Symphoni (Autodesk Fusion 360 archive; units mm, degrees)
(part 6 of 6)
sketch "Sketch4" plane through (0, -1, 0) normal (0, -1, 0) x axis (1, 0, 0)
  line L1 (0, 5) -> (0, 35)
  line L2 (105, 0) -> (5, 0)
  line L3 (110, 35) -> (110, 5)
  line L4 (5, 40) -> (105, 40)
  line L5 (54.65, 25.9017) -> (54.65, 36.5017)
  line L6 (45.35, 25.9017) -> (54.65, 25.9017)
  line L7 (45.35, 36.5017) -> (45.35, 25.9017)
  line L8 (53.95, 37.2017) -> (46.05, 37.2017)
  line L9 (74.82, 26.0167) -> (28.79, 26.0167)
  line L10 (28.79, 26.0167) -> (74.82, 26.0167)
  line L11 (51, 26.0167) -> (49, 26.0167)
  line L12 (51, 26.0167) -> (49, 26.0167)
  line L13 (35.39, 26.0167) -> (32.29, 26.0167)
  line L14 (70.38, 26.0167) -> (67.28, 26.0167)
  line L15 (74.82, 24.5067) -> (28.79, 24.5067)
  line L16 (28.79, 24.5067) -> (74.82, 24.5067)
  line L17 (51, 24.5067) -> (49, 24.5067)
  line L18 (51, 24.5067) -> (49, 24.5067)
  line L19 (35.39, 24.5067) -> (32.29, 24.5067)
  line L20 (70.38, 24.5067) -> (67.28, 24.5067)
  line L21 (86.536, 12.3973) -> (88.536, 12.3973)
  line L22 (86.536, 12.3973) -> (88.536, 12.3973)
  line L23 (31.001, 12.3973) -> (86.536, 12.3973)
  line L24 (29.001, 12.3973) -> (31.001, 12.3973)
  line L25 (29.001, 12.3973) -> (31.001, 12.3973)
  line L26 (86.536, 12.3973) -> (31.001, 12.3973)
  line L27 (36.646, 12.3973) -> (33.446, 12.3973)
  line L28 (47.606, 12.3973) -> (49.006, 12.3973)
  line L29 (50.146, 12.3973) -> (51.546, 12.3973)
  line L30 (52.686, 12.3973) -> (54.086, 12.3973)
  line L31 (74.256, 12.3973) -> (75.656, 12.3973)
  line L32 (74.256, 12.3973) -> (75.656, 12.3973)
  line L33 (74.256, 12.3973) -> (75.656, 12.3973)
  line L34 (85.736, 12.3973) -> (82.536, 12.3973)
  line L35 (74.256, 12.3973) -> (75.656, 12.3973)
  line L36 (74.256, 12.3973) -> (75.656, 12.3973)
  line L37 (74.256, 12.3973) -> (75.656, 12.3973)
  line L38 (36.736, 12.3973) -> (33.536, 12.3973)
  line L39 (78.096, 12.3973) -> (74.896, 12.3973)
  line L40 (86.536, 10.8873) -> (31.001, 10.8873)
  line L41 (74.82, 26.0167) -> (28.79, 26.0167)
  line L42 (74.82, 24.5067) -> (74.82, 26.0167)
  line L43 (28.79, 24.5067) -> (74.82, 24.5067)
  line L44 (28.79, 26.0167) -> (28.79, 24.5067)
  line L45 (86.536, 12.3973) -> (29.001, 12.3973)
  line L46 (86.536, 10.8873) -> (86.536, 12.3973)
  line L47 (29.001, 10.8873) -> (86.536, 10.8873)
  line L48 (29.001, 12.3973) -> (29.001, 10.8873)
  line L49 (35.39, 26.0167) -> (32.29, 26.0167)
  line L50 (36.646, 12.3973) -> (33.446, 12.3973)
  line L51 (36.736, 12.3973) -> (33.536, 12.3973)
  line L52 (85.736, 12.3973) -> (82.536, 12.3973)
  line L53 (78.096, 12.3973) -> (74.896, 12.3973)
  line L54 (37.4, 26.1067) -> (30.4005, 26.1067)
  line L55 (37.4, 29.975) -> (37.4, 26.1067)
  line L56 (30.4012, 29.975) -> (37.4, 29.975)
  line L57 (30.4012, 25.975) -> (30.4012, 29.975)
  line L58 (37.4313, 24.5067) -> (30.4313, 24.5067)
  line L59 (37.4313, 20.5067) -> (37.4313, 24.5067)
  line L60 (30.4313, 20.5067) -> (37.4313, 20.5067)
  line L61 (30.4313, 24.5067) -> (30.4313, 20.5067)
  line L62 (72.5068, 30.1067) -> (65.5068, 30.1067)
  line L63 (72.5068, 26.1067) -> (72.5068, 30.1067)
  line L64 (65.5068, 26.1067) -> (72.5068, 26.1067)
  line L65 (65.5068, 30.1067) -> (65.5068, 26.1067)
  line L66 (72.5068, 24.5067) -> (65.5068, 24.5067)
  line L67 (72.5068, 20.5067) -> (72.5068, 24.5067)
  line L68 (65.5068, 20.5067) -> (72.5068, 20.5067)
  line L69 (65.5068, 24.5067) -> (65.5068, 20.5067)
  line L70 (38.709, 12.3973) -> (31.709, 12.3973)
  line L71 (38.709, 15.3973) -> (38.709, 12.3973)
  line L72 (31.709, 15.3973) -> (38.709, 15.3973)
  line L73 (31.709, 12.3973) -> (31.709, 15.3973)
  line L74 (38.7054, 10.8873) -> (31.7054, 10.8873)
  line L75 (38.7054, 6.8873) -> (38.7054, 10.8873)
  line L76 (31.7054, 6.8873) -> (38.7054, 6.8873)
  line L77 (31.7054, 10.8873) -> (31.7054, 6.8873)
  arc A1 centre (5, 35) radius 5 clockwise from (0, 35) to (5, 40)
  arc A2 centre (5, 5) radius 5 clockwise from (5, 0) to (0, 5)
  arc A3 centre (105, 5) radius 5 clockwise from (110, 5) to (105, 0)
  arc A4 centre (105, 35) radius 5 clockwise from (105, 40) to (110, 35)
  arc A5 centre (46.05, 36.5017) radius 0.7 clockwise from (45.35, 36.5017) to (46.05, 37.2017)
  arc A6 centre (53.95, 36.5017) radius 0.7 clockwise from (53.95, 37.2017) to (54.65, 36.5017)
  circle C1 centre (50, 17.3288) radius 2.7
  point P31 (74.82, 24.5067)
  point P62 (74.82, 24.5067)
  point P22 (28.79, 26.0167)
  point P60 (28.79, 26.0167)
  point P59 (86.536, 10.8873)
  point P66 (86.536, 10.8873)
  point P41 (29.001, 12.3973)
  point P64 (29.001, 12.3973)
  point P82 (30.4313, 24.5067)
  point P90 (65.5068, 24.5067)
  point P94 (31.709, 12.3973)
  point P98 (31.7054, 10.8873)
  point P78 (30.4012, 25.975)
  point P79 (37.4, 26.1067)
  point P81 (30.4012, 29.975)
  point P83 (37.4313, 24.5067)
  point P85 (30.4313, 20.5067)
  point P86 (65.5068, 30.1067)
  point P87 (72.5068, 30.1067)
  point P89 (65.5068, 26.1067)
  point P91 (72.5068, 24.5067)
  point P93 (65.5068, 20.5067)
  point P95 (38.709, 12.3973)
  point P97 (31.709, 15.3973)
  point P99 (38.7054, 10.8873)
  point P101 (31.7054, 6.8873)
  horizontal L41
  vertical L42
  horizontal L43
  vertical L44
  coincident P31 P62
  coincident P22 P60
  horizontal L45
  vertical L46
  horizontal L47
  vertical L48
  coincident P59 P66
  coincident P41 P64
  horizontal L54
  vertical L55
  horizontal L56
  vertical L57
  horizontal L58
  vertical L59
  horizontal L60
  vertical L61
  coincident L43 P82
  horizontal L62
  vertical L63
  horizontal L64
  vertical L65
  horizontal L66
  vertical L67
  horizontal L68
  vertical L69
  coincident L43 P90
  horizontal L70
  vertical L71
  horizontal L72
  vertical L73
  coincident L23 P94
  horizontal L74
  vertical L75
  horizontal L76
  vertical L77
  coincident L40 P98
  collinear L65 L69
  dimension "d18" distance P78 P79 = 7
  dimension "d19" distance P78 P81 = 4
  dimension "d20" distance P82 P83 = 7
  dimension "d21" distance P82 P85 = 4
  dimension "d28" distance P86 P87 = 7
  dimension "d29" distance P86 P89 = 4
  dimension "d30" distance P90 P91 = 7
  dimension "d31" distance P90 P93 = 4
  dimension "d40" distance P94 P95 = 7
  dimension "d41" distance P94 P97 = 3
  dimension "d46" distance P98 P99 = 7
  dimension "d47" distance P98 P101 = 4
  dimension "d50" distance L43 L64 = 1.6
  dimension "d51" distance L43 L54 = 1.6
extrude "Extrude5" add sketch "Sketch4" profile of A6 L15 L16 L19 L20 L43 L58 L59 L60 L61 L66 L67 L68 L69 along normal blind 32
fillet "Fillet3" radius 2.5
fillet "Fillet4" radius 6
sketch "Sketch5" plane through (0, 0, 28.0167) normal (0, 0, 1) x axis (-1, 0, 0)
  line L1 (-30.473, 6) -> (-37.473, 6)
  line L2 (-30.473, 33) -> (-30.473, 6)
  line L3 (-37.473, 33) -> (-30.473, 33)
  line L4 (-37.473, 6) -> (-37.473, 33)
  circle C1 centre (-33.84, 30.11) radius 1.55
  circle C2 centre (-68.83, 30.11) radius 1.55
extrude "Extrude6" cut sketch "Sketch5" profile of C1 C2 against normal blind 8
sketch "Sketch6" plane through (0, 0, 12.3973) normal (0, 0, 1) x axis (-1, 0, 0)
  line L1 (-88.536, 4.4475) -> (-88.536, 48.4475)
  line L2 (-31.001, 2.4475) -> (-86.536, 2.4475)
  line L3 (-29.001, 48.4475) -> (-29.001, 4.4475)
  line L4 (-86.536, 50.4475) -> (-31.001, 50.4475)
  line L5 (-5, 1) -> (-5, 0)
  line L6 (-105, 1) -> (-5, 1)
  line L7 (-105, 0) -> (-105, 1)
  line L8 (-5, 0) -> (-105, 0)
  line L9 (-81, 13) -> (-81, 1)
  line L10 (-72.7669, 34.5764) -> (-81, 13)
  line L11 (-78.3852, 36.7202) -> (-72.7669, 34.5764)
  line L12 (-87.4363, 13) -> (-78.3852, 36.7202)
  line L13 (-87.4363, 1) -> (-87.4363, 13)
  arc A1 centre (-86.536, 48.4475) radius 2 clockwise from (-88.536, 48.4475) to (-86.536, 50.4475)
  arc A2 centre (-86.536, 4.4475) radius 2 clockwise from (-86.536, 2.4475) to (-88.536, 4.4475)
  arc A3 centre (-31.001, 4.4475) radius 2 clockwise from (-29.001, 4.4475) to (-31.001, 2.4475)
  arc A4 centre (-31.001, 48.4475) radius 2 clockwise from (-31.001, 50.4475) to (-29.001, 48.4475)
  circle C1 centre (-35.046, 9.8275) radius 1.6
  circle C2 centre (-48.306, 17.4675) radius 0.7
  circle C3 centre (-50.846, 17.4675) radius 0.7
  circle C4 centre (-53.386, 17.4675) radius 0.7
  circle C5 centre (-74.956, 4.1575) radius 0.7
  circle C6 centre (-74.956, 6.6975) radius 0.7
  circle C7 centre (-74.956, 9.2375) radius 0.7
  circle C8 centre (-84.136, 10.4175) radius 1.6
  circle C9 centre (-74.956, 11.7775) radius 0.7
  circle C10 centre (-74.956, 14.3175) radius 0.7
  circle C11 centre (-74.956, 16.8575) radius 0.7
  circle C12 centre (-35.136, 26.4875) radius 1.6
  circle C13 centre (-76.496, 33.2075) radius 1.6
  point P31 (-81, 1)
  point P36 (-87.4363, 1)
  coincident L6 P31
  perpendicular L6 L9
  perpendicular L10 L11
  perpendicular L11 L12
  coincident L6 P36
  perpendicular L6 L13
extrude "Extrude7" add sketch "Sketch6" profile of A2 L2 C8 C13 L6 L9 L10 L11 L12 L13 along normal blind 4
fillet "Fillet5" radius 2
extrude "Extrude8" add sketch "Sketch4" profile of A6 L23 L26 L27 L38 L40 L45 L47 L50 L51 L70 L71 L72 L73 L74 L75 L76 L77 along normal blind 29
fillet "Fillet6" radius 1.5 5
extrude "Extrude9" new body sketch "Sketch6" profile of A2 L2 C8 C13 L6 L9 L10 L11 L12 L13 blind -4 from offset -1.6
fillet "Fillet7" radius 1
extrude "Extrude10" cut sketch "Sketch6" profile of C1 C12 along normal blind 5 and against normal blind 10
sketch "Sketch7" plane through (0, -1, 0) normal (0, -1, 0) x axis (1, 0, 0)
  line L1 (31.7054, 10.8873) -> (31.7054, 1.8873)
  line L2 (38.7054, 10.8873) -> (31.7054, 10.8873)
  line L3 (38.7054, 1.8873) -> (38.7054, 10.8873)
  line L4 (31.7054, 1.8873) -> (38.7054, 1.8873)
  line L5 (38.709, 12.3973) -> (38.709, 16.8973)
  line L6 (31.709, 12.3973) -> (38.709, 12.3973)
  line L7 (31.709, 16.8973) -> (31.709, 12.3973)
  line L8 (38.709, 16.8973) -> (31.709, 16.8973)
  line L9 (87.4363, 12.3973) -> (87.4363, 18.3973)
  line L10 (81, 12.3973) -> (87.4363, 12.3973)
  line L11 (81, 18.3973) -> (81, 12.3973)
  line L12 (87.4363, 18.3973) -> (81, 18.3973)
  line L13 (65.5068, 24.5067) -> (65.5068, 14.5067)
  line L14 (72.5068, 24.5067) -> (65.5068, 24.5067)
  line L15 (72.5068, 14.5067) -> (72.5068, 24.5067)
  line L16 (65.5068, 14.5067) -> (72.5068, 14.5067)
  line L17 (30.4313, 24.5067) -> (30.4313, 18.0067)
  line L18 (37.4313, 24.5067) -> (30.4313, 24.5067)
  line L19 (37.4313, 18.0067) -> (37.4313, 24.5067)
  line L20 (30.4313, 18.0067) -> (37.4313, 18.0067)
  line L21 (0, 5) -> (0, 35)
  line L22 (105, 0) -> (5, 0)
  line L23 (110, 35) -> (110, 5)
  line L24 (5, 40) -> (105, 40)
  line L25 (54.65, 25.9017) -> (54.65, 36.5017)
  line L26 (45.35, 25.9017) -> (54.65, 25.9017)
  line L27 (45.35, 36.5017) -> (45.35, 25.9017)
  line L28 (53.95, 37.2017) -> (46.05, 37.2017)
  line L29 (50.0506, 0) -> (50.0506, 40)
  line L30 (-2.4494, 0) -> (102.5506, 0)
  line L31 (-2.4494, 40) -> (-2.4494, 0)
  line L32 (102.5506, 40) -> (-2.4494, 40)
  line L33 (102.5506, 0) -> (102.5506, 40)
  line L34 (-2.4494, 40) -> (102.5506, 0)
  line L35 (102.5506, 40) -> (-2.4494, 0)
  arc A1 centre (5, 35) radius 5 clockwise from (0, 35) to (5, 40)
  arc A2 centre (5, 5) radius 5 clockwise from (5, 0) to (0, 5)
  arc A3 centre (105, 5) radius 5 clockwise from (110, 5) to (105, 0)
  arc A4 centre (105, 35) radius 5 clockwise from (105, 40) to (110, 35)
  arc A5 centre (46.05, 36.5017) radius 0.7 clockwise from (45.35, 36.5017) to (46.05, 37.2017)
  arc A6 centre (53.95, 36.5017) radius 0.7 clockwise from (53.95, 37.2017) to (54.65, 36.5017)
  circle C1 centre (50, 17.3288) radius 2.7
  point P42 (50.0506, 40)
  point P43 (50.0506, 0)
  point P48 (50.0506, 20)
  point P44 (102.5506, 0)
  point P46 (-2.4494, 40)
  point P47 (102.5506, 40)
  coincident L24 P42
  coincident L22 P43
  perpendicular L22 L29
  horizontal L30
  perpendicular L30 L31
  parallel L30 L32
  parallel L31 L33
  coincident L34 P48
  coincident L35 P48
  coincident L22 P44
  midpoint L29 P48
  dimension "d67" distance P46 P47 = 105
extrude "Extrude11" cut sketch "Sketch7" profile of L22 A3 L23 A4 L24 L33 against normal blind 15
fillet "Fillet8" radius 5
extrude "Extrude12" cut sketch "Sketch7" profile of L22 A3 L23 A4 L24 L33 against normal blind 15
extrude "Extrude13" add sketch "Sketch7" profile of A1 L21 A2 L30 L31 L32 against normal blind 1
fillet "Fillet9" radius 5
